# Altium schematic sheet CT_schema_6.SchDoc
size 277 x 170 mm
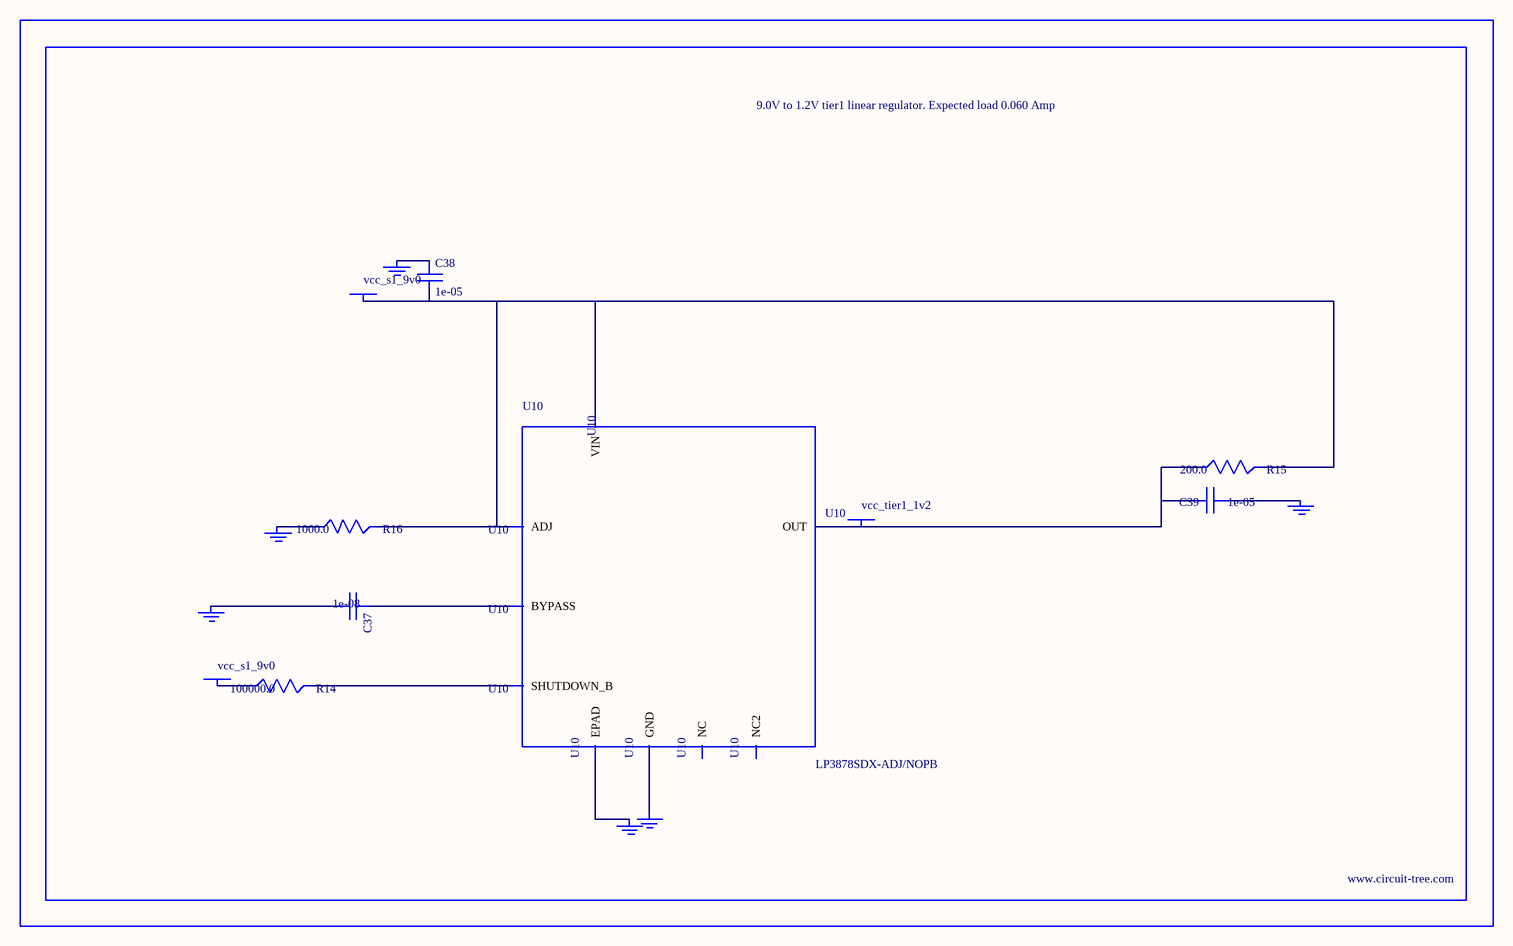
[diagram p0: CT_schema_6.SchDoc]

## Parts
BORDER5  (no value)
C37  1e-08  [C0402]
C38  1e-05  [C1206]
C39  1e-05  [C0805]
GND_INSTANCE_5_0  (no value)
GND_INSTANCE_5_1  (no value)
GND_INSTANCE_5_2  (no value)
GND_INSTANCE_5_3  (no value)
GND_INSTANCE_5_4  (no value)
GND_INSTANCE_5_5  (no value)
POWER_INSTANCE_5_0  vcc_s1_9v0
POWER_INSTANCE_5_1  vcc_s1_9v0
POWER_INSTANCE_5_2  vcc_tier1_1v2
R14  100000.0  [R0603]
R15  200.0  [R0603]
R16  1000.0  [R0603]
U10  LP3878SDX-ADJ/NOPB  [WSON-8]

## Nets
NetC37_1: C37.1 U10.1(BYPASS)
NetC37_2: C37.2 GND_INSTANCE_5_0.0(GND)
NetC38_1: C38.1 GND_INSTANCE_5_1.0(GND)
NetC38_2: C38.2 POWER_INSTANCE_5_0.0(PWR) R15.2 R16.2 U10.4(VIN) U10.6(ADJ)
NetC39_1: C39.1 GND_INSTANCE_5_2.0(GND)
NetC39_2: C39.2 POWER_INSTANCE_5_2.0(PWR) R15.1 U10.5(OUT)
NetGND_INSTANCE_5_3_0: GND_INSTANCE_5_3.0(GND) R16.1
NetGND_INSTANCE_5_4_0: GND_INSTANCE_5_4.0(GND) U10.PAD(EPAD)
NetGND_INSTANCE_5_5_0: GND_INSTANCE_5_5.0(GND) U10.3(GND)
NetPOWER_INSTANCE_5_1_0: POWER_INSTANCE_5_1.0(PWR) R14.1
NetR14_2: R14.2 U10.8(SHUTDOWN_B)

Not connected (* = marked no-connect by the designer): U10 2(NC) 7(NC2)

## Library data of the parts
BORDER5 = BORDER_PAGE5
C37 = C0402C103K3RAC
C38 = C1206C106K3RACTU
C39 = GRM219R60J106ME19D
GND_INSTANCE_5_0-GND_INSTANCE_5_5 = GND
POWER_INSTANCE_5_0-POWER_INSTANCE_5_2 = PWR
R14 = RC0603JR-07100KL
R15 = RC0603JR-07200RL
R16 = RC0603JR-071KL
